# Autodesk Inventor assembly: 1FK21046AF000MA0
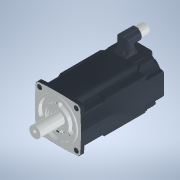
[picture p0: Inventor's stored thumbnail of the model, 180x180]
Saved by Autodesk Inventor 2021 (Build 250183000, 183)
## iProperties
Category: PARTsolutions
Created: 2026-06
Part Number: 1FK21046AF000MA0
Catalog Web Link: www.3dfindit.com
Description: 1FK21046AF000MA0-Servo synchronous motor
Document SubType Name: Assembly
Designer: psAdmin
Mass: 827.143 g
Surface Area: 1124.16 cm^2
Volume: 827.143 cm^3
Density: 1 g/cm^3
Title: 1FK21046AF000MA0
Author: Cadenas PARTsolutions
Comments: Servo synchronous motor
PSOL_IDENT_0: {$CADENAS_DATA/23d-libs/siemens_ag/_cat_/1c/1f/1fk21046af000ma0.prj},193 {STYP=ASS},{VTYP=3D},{NB=1F
PSOL_IDENT_1: K21046AF000MA0},{LINA=1FK21046AF000MA0},{NN=1FK21046AF000MA0},{DATE=19.08.2025 14:00:28},{GEOMDATE=3
PSOL_IDENT_2: 0.07.2025 02:02:08},{VERSION=},{LINEID=10},{WBVAR=},{WBNUMERIC=}  {NB=1FK21046AF000MA0},{LINA=1FK210
PSOL_IDENT_3: 46AF000MA0},{KT=DUMMY},{PREVIEW=../../../_pool_/cb/72/p_d211_xx_00434j.png},{DESCSHORT=SIMOTICS S-1F
PSOL_IDENT_4: K2 HD, SINAMICS S210 3AC 400V-480V, 3.2 Nm, 3000 rpm},{DESCLONG=SIMOTICS S-1FK2 HD servo motor M0=3.
PSOL_IDENT_5: 2 Nm; PN = 1 kW at nN=3000 rpm (380-480 V); PN = 0.5 kW at nN=1500 rpm (200-240 V); degree of protec
PSOL_IDENT_6: tion IP64; cylindrical shaft D19x40mm; absolute encoder 22-bit + 12-bit multiturn (encoder AM22DQC);
PSOL_IDENT_7: with OCC interface; plug size M17, rotatable; SIMOTICS S-1FK2 servomotorfor a wide range of uses in
PSOL_IDENT_8: industrial environments. SIMOTICS S‑1FK2 servomotors are compact synchronous motors with a high dyn
PSOL_IDENT_9: amic performance that set themselves apart as a result of their high power density, degree of protec
PSOL_IDENT_10: tion and overload capability. The motors are available in two variants: as High Dynamic variant (hig
PSOL_IDENT_11: hest dynamic performance as a result of the low intrinsic moment of inertia for applications demandi
PSOL_IDENT_12: ng a high dynamic performance with low moved masses) - and as Compact variant (precise and stable cl
PSOL_IDENT_13: osed-loop control for medium up to large moved masses as a result of a medium intrinsic moment of in
PSOL_IDENT_14: ertia). SIMOTICSS‑1FK2 servomotors fully exploit their strengths in a system with the SINAMICSS210 f
PSOL_IDENT_15: requency converter and simple connection using the one cable connection (OCC). Advantages include th
PSOL_IDENT_16: e short control and positioning times, fast and precise correction of disturbing quantities as well
PSOL_IDENT_17: as stable control with a high dynamic performance. The servo motors can be configured to address a w
PSOL_IDENT_18: ide range of requirements. For example with and without holding brake, IP64 or IP65 degree of protec
PSOL_IDENT_19: tion, singleturn or multiturn absolute encoders - to name just a few. Further, the servomotors are a
PSOL_IDENT_20: vailable in different shaft heights extending from 20 to 100. A shaft sealing ring is available to a
PSOL_IDENT_21: chieve an IP65 degree of protection and for subsequent mounting at the motor or as spare part. SIMOT
PSOL_IDENT_22: ICS - the optimum motor for each and every motion control application.},{INTNO=195125049666},{SUPPLI
PSOL_IDENT_23: ERALTNO=1FK2104-6AF00-0MA0},{MANUID=1FK21046AF000MA0},{MANUNAME=Siemens},{MANUTYPEDESC=Synchronous m
PSOL_IDENT_24: otor 1FK2-HD 3.2 NM},{AAU732=SIMOTICS},{AAO057=S-1FK2},{AAU734=SIMOTICS S-1FK2 HD servo motor M0=3.2
PSOL_IDENT_25: Nm; PN = 1 kW at nN=3000 rpm (380-480 V); PN = 0.5 kW at nN=1500 rpm (200-240 V); degree of protect
PSOL_IDENT_26: ion IP64; cylindrical shaft D19x40mm; absolute encoder 22-bit + 12-bit multiturn (encoder AM22DQC);
PSOL_IDENT_27: with OCC interface; plug size M17, rotatable;},{AAW338=Synchronous motor 1FK2-HD 3.2 NM},{AAO742=SIM
PSOL_IDENT_28: OTICS},{AAO663=4042948694374},{NOCUPEROU=1},{PRICEQUANTITY=1},{QUANTITYMIN=1},{QUANTITYINT=1},{CTN=8
PSOL_IDENT_29: 5015220},{COO=DE},{AAO676=1FK2104-6AF00-0MA0},{AAO677=Siemens AG},{ORDERUNIT=C62},{CONTENTUNIT=C62}
NB: 1FK21046AF000MA0
NN: 1FK21046AF000MA0
NT: Servo synchronous motor
NBSYN: $MANUID.
LINA: 1FK21046AF000MA0
CATALOG: SIEMENS
PREVIEW: ../../../_pool_/cb/72/p_d211_xx_00434j.png
DESCSHORT: SIMOTICS S-1FK2 HD, SINAMICS S210 3AC 400V-480V, 3.2 Nm, 3000 rpm
DESCLONG: SIMOTICS S-1FK2 HD servo motor M0=3.2 Nm; PN = 1 kW at nN=3000 rpm (380-480 V); PN = 0.5 kW at nN=1500 rpm (200-240 V); degree of protection IP64; cylindrical s
INTNO: 195125049666
SUPPLIERALTNO: 1FK2104-6AF00-0MA0
MANUID: 1FK21046AF000MA0
MANUNAME: Siemens
MANUTYPEDESC: Synchronous motor 1FK2-HD 3.2 NM
AAU732: SIMOTICS
AAO057: S-1FK2
AAU734: SIMOTICS S-1FK2 HD servo motor M0=3.2 Nm; PN = 1 kW at nN=3000 rpm (380-480 V); PN = 0.5 kW at nN=1500 rpm (200-240 V); degree of protection IP64; cylindrical s
AAW338: Synchronous motor 1FK2-HD 3.2 NM
AAO742: SIMOTICS
AAO663: 4042948694374.0
NOCUPEROU: 1
PRICEQUANTITY: 1
QUANTITYMIN: 1
QUANTITYINT: 1
CTN: 85015220
COO: DE
ARTICLENO: 1FK21046AF000MA0
BOMINFO: 1FK21046AF000MA0
CREATOR: CADENAS GmbH
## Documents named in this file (24)
- e:\temp\worker_COMMON_23\temp\tmp_3608_8_u6XPB\format_0\1FK21046AF000MA0.iam
- e:\temp\worker_COMMON_23\temp\tmp_3608_8_u6XPB\format_0\1FK21046AF000MA0_PART1.ipt
- e:\temp\worker_COMMON_23\temp\tmp_3608_8_u6XPB\format_0\1FK21046AF000MA0_PART2.ipt
- e:\temp\worker_COMMON_23\temp\tmp_3608_8_u6XPB\format_0\1FK21046AF000MA0_PART3.ipt
- e:\temp\worker_COMMON_23\temp\tmp_3608_8_u6XPB\format_0\1FK21046AF000MA0_PART4.ipt
- e:\temp\worker_COMMON_23\temp\tmp_3608_8_u6XPB\format_0\1FK21046AF000MA0_PART5.ipt
- e:\temp\worker_COMMON_23\temp\tmp_3608_8_u6XPB\format_0\1FK21046AF000MA0_PART6.ipt
- e:\temp\worker_COMMON_23\temp\tmp_3608_8_u6XPB\format_0\1FK21046AF000MA0_PART7.ipt
- e:\temp\worker_COMMON_23\temp\tmp_3608_8_u6XPB\format_0\1FK21046AF000MA0_PART8.ipt
- e:\temp\worker_COMMON_23\temp\tmp_3608_8_u6XPB\format_0\1FK21046AF000MA0_PART9.ipt
- e:\temp\worker_COMMON_23\temp\tmp_3608_8_u6XPB\format_0\1FK21046AF000MA0_PART10.ipt
- e:\temp\worker_COMMON_23\temp\tmp_3608_8_u6XPB\format_0\1FK21046AF000MA0_PART11.ipt
- e:\temp\worker_COMMON_23\temp\tmp_3608_8_u6XPB\format_0\1FK21046AF000MA0_PART12.ipt
- e:\temp\worker_COMMON_23\temp\tmp_3608_8_u6XPB\format_0\1FK21046AF000MA0_PART13.ipt
- e:\temp\worker_COMMON_23\temp\tmp_3608_8_u6XPB\format_0\1FK21046AF000MA0_PART14.ipt
- e:\temp\worker_COMMON_23\temp\tmp_3608_8_u6XPB\format_0\1FK21046AF000MA0_PART15.ipt
- e:\temp\worker_COMMON_23\temp\tmp_3608_8_u6XPB\format_0\1FK21046AF000MA0_PART16.ipt
- e:\temp\worker_COMMON_23\temp\tmp_3608_8_u6XPB\format_0\1FK21046AF000MA0_PART17.ipt
- e:\temp\worker_COMMON_23\temp\tmp_3608_8_u6XPB\format_0\1FK21046AF000MA0_PART18.ipt
- e:\temp\worker_COMMON_23\temp\tmp_3608_8_u6XPB\format_0\1FK21046AF000MA0_PART19.ipt
- e:\temp\worker_COMMON_23\temp\tmp_3608_8_u6XPB\format_0\1FK21046AF000MA0_PART20.ipt
- e:\temp\worker_COMMON_23\temp\tmp_3608_8_u6XPB\format_0\1FK21046AF000MA0_PART21.ipt
- e:\temp\worker_COMMON_23\temp\tmp_3608_8_u6XPB\format_0\1FK21046AF000MA0_PART22.ipt
- e:\temp\worker_COMMON_23\temp\tmp_3608_8_u6XPB\format_0\1FK21046AF000MA0_PART23.ipt
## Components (23 placed, 23 different names)
1. 1FK21046AF000MA0_PART1:1
2. 1FK21046AF000MA0_PART2:1
3. 1FK21046AF000MA0_PART3:1
4. 1FK21046AF000MA0_PART4:1
5. 1FK21046AF000MA0_PART5:1
6. 1FK21046AF000MA0_PART6:1
7. 1FK21046AF000MA0_PART7:1
8. 1FK21046AF000MA0_PART8:1
9. 1FK21046AF000MA0_PART9:1
10. 1FK21046AF000MA0_PART10:1
11. 1FK21046AF000MA0_PART11:1
12. 1FK21046AF000MA0_PART12:1
13. 1FK21046AF000MA0_PART13:1
14. 1FK21046AF000MA0_PART14:1
15. 1FK21046AF000MA0_PART15:1
16. 1FK21046AF000MA0_PART16:1
17. 1FK21046AF000MA0_PART17:1
18. 1FK21046AF000MA0_PART18:1
19. 1FK21046AF000MA0_PART19:1
20. 1FK21046AF000MA0_PART20:1
21. 1FK21046AF000MA0_PART21:1
22. 1FK21046AF000MA0_PART22:1
23. 1FK21046AF000MA0_PART23:1
